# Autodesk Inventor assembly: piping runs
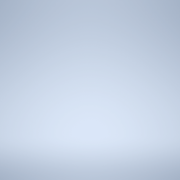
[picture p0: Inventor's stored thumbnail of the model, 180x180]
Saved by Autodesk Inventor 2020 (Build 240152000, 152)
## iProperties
ActiveState: False
Angle: UnInitValue
BendRadius: 12,700 mm
CouplingKey: UnInitValue
DefaultBendRadius: UnInitValue
Diameter: 1/2
DiameterType: Nominal
Elbow45Key: UnInitValue
Elbow90Key: UnInitValue
ElbowCustomKey: UnInitValue
EndFittingKey: v3#933069c9-73b6-4141-af99-628d4a97b2c2#1
Ending: UnInitValue
FittingMaterial: UnInitValue
FittingStandard: UnInitValue
FlangeKey: UnInitValue
Gap: UnInitValue
GasketKey: UnInitValue
ID: 1,27
IntermediateSegmentsInc: UnInitValue
IntermediateSegmentsMax: UnInitValue
IntermediateSegmentsMin: UnInitValue
IsButtWelded: UnInitValue
IsFlanged: UnInitValue
IsSelfDraining: UnInitValue
Material: UnInitValue
MixedUnits: UnInitValue
Name: Hydraulická hadice - SAE přírubové spojky
OD: 2,2352
PipeKey: v3#d489867e-ac9b-47ea-b952-0a1b885f66be#4
PipeType: Flexible Hose
PipingComponentColor: As Material
RoundUpValue: 3,175 mm
RouteDirection45: UnInitValue
RouteDirection90: UnInitValue
Schedule: ID=0.5
ShowGap: UnInitValue
Standard: UnInitValue
StartFittingKey: v3#933069c9-73b6-4141-af99-628d4a97b2c2#1
SuppressEndFitting: False
SuppressStartFitting: False
TerminationSegmentsInc: UnInitValue
TerminationSegmentsMax: UnInitValue
TerminationSegmentsMin: UnInitValue
UseFlangsForCouplings: UnInitValue
UseSubASM: True
_ComponentInfo: <CS><C N="Pipe" R="1.117600" OR="1.117600" IR="0.635000" PL="PL" PartType="" SymKey="" PN="Parker Hydraulic Hose - No Skive 1/2"><CO N="1"><FE V="0"/><FD V="0"/
BendRadius: UnInitValue
Diameter: M40
Elbow45Key: v3#97879d80-057e-491b-840b-74a9b3a7cf63#17
Elbow90Key: v3#ace818b0-7b7c-4ad9-b19c-6da358a202c1#17
EndFittingKey: UnInitValue
ID: UnInitValue
IntermediateSegmentsInc: 1,000 mm
IntermediateSegmentsMax: 5000,000 mm
IntermediateSegmentsMin: 60,000 mm
IsButtWelded: False
IsFlanged: False
IsSelfDraining: False
MixedUnits: False
Name: DIN 2458/DIN 2605 -Ocelové potrubí svařované a tvarovky
OD: UnInitValue
PipeKey: v3#dcef2839-8903-4c98-a96c-b861f5d9bb7f#98
PipeType: Rigid Pipe
RoundUpValue: UnInitValue
RouteDirection45: True
RouteDirection90: True
Schedule: ID=30.7
StartFittingKey: UnInitValue
SuppressEndFitting: UnInitValue
SuppressStartFitting: UnInitValue
TerminationSegmentsInc: 1,000 mm
TerminationSegmentsMax: 5000,000 mm
TerminationSegmentsMin: 60,000 mm
UseSubASM: UnInitValue
_ComponentInfo: <CS><C N="Pipe" R="2.415000" IR="1.535000" PL="PL" PN="DIN 2458 Pipe 48.3 x 8.8"><CO N="1"><FE V="2"/><FD V="0"/><ET V="Welded"/><NS V="M40"/><MA V="0.000000"/>
CouplingKey: v3#29993622-4c6a-437e-8b8c-43a0846f8735#1
Elbow45Key: v3#d7b5d569-4a12-4d65-ba55-12203d6ac7ed#1
Elbow90Key: v3#25d2a8db-6517-4627-a5a4-9d27e4d26b9b#1
IntermediateSegmentsInc: 2,540 mm
IntermediateSegmentsMax: 2540,000 mm
IntermediateSegmentsMin: 25,400 mm
Name: ASTM D 1785-ASTM D 2466 -  PVC potrubí spojované a tvarovky
PipeKey: v3#4bf12049-4375-491b-8f13-d4ee0c517c57#1
Schedule: 40
TerminationSegmentsInc: 2,540 mm
TerminationSegmentsMax: 2540,000 mm
TerminationSegmentsMin: 25,400 mm
_ComponentInfo: <CS><C N="Pipe" R="1.066800" IR="0.789940" PL="PL" PN="ASTM D 1785 Pipe 1/2 - Schedule 40"><CO N="1"><FE V="0"/><FD V="0"/><ET V="Jointed"/><NS V="1/2"/><MA V="
CouplingKey: v3#ed415c76-4cec-44a3-ba67-72e47bf70384#4
Elbow45Key: v3#2e5fd082-3851-4eb0-bde1-6c7078a7d72b#4
Elbow90Key: v3#82a08401-12d7-413b-b7f9-9cf3b607be7b#4
IntermediateSegmentsMax: 5080,000 mm
Name: ASTM A53/A53M-ASME B16.11 - Ocelové potrubí svařované
PipeKey: v3#4ce5e9fa-6da0-4801-ac02-ee7a0fb518d6#7
TerminationSegmentsMax: 5080,000 mm
_ComponentInfo: <CS><C N="Pipe" R="1.066800" IR="0.789940" PL="PL" PN="ASTM A 53/A 53M Pipe 1/2 - Schedule 40"><CO N="1"><FE V="0"/><FD V="0"/><ET V="Welded"/><NS V="1/2"/><MA 
CouplingKey: v3#b06656e5-2b55-488c-bcf0-6a90c79c4683#2
Elbow45Key: v3#421a8b99-1721-409a-bc3b-c00889561754#1
Elbow90Key: v3#17490b17-1dd8-40fc-8de7-1a70c3bab2d7#1
Name: ISO 4065-ISO 3633 - PVC potrubí a tvarovky
PipeKey: v3#4f84f716-5ba0-45ef-967a-c32c3d7345ce#70
Schedule: S40
_ComponentInfo: <CS><C N="Pipe" R="2.000000" IR="1.950000" PL="PL" PN="ISO 4065 Pipe 40 x 0.5 S40"><CO N="1"><FE V="0"/><FD V="0"/><ET V="Jointed"/><NS V="M40"/><MA V="6.000000
CouplingKey: v3#771d4942-b9e7-43bc-9d41-ab12a9580492#3
Elbow45Key: v3#626cc28c-1a24-4045-be0d-40d896dc828d#3
Elbow90Key: v3#bc6b44ab-9235-4590-b699-74498030a1ff#3
IntermediateSegmentsMin: 50,800 mm
Name: ANSI/ASME B36.19M-ASME B16.3 - Potrubí se závity a litinovými tvarovkami
PipeKey: v3#323c0148-c750-449d-a0c6-11721f2a5046#1
Schedule: 40S
TerminationSegmentsMin: 50,800 mm
_ComponentInfo: <CS><C N="Pipe" R="1.066800" IR="0.789940" PL="PL" PN="ANSI/ASME B36.19M Pipe with Threaded Ends 1/2 - Schedule 40S"><CO N="1"><FE V="0"/><FD V="1"/><ET V="Thre
CouplingKey: v3#181262db-c004-4877-bc40-c64b931a44f6#3
Elbow45Key: v3#960407aa-00b9-4d72-aae7-d50595845cfd#3
Elbow90Key: v3#6c92b367-65e9-486b-b952-db434ae2548d#3
IntermediateSegmentsMin: 20,000 mm
Name: JIS G 3442/JIS B 2301  Ocelové potrubí se závity a litinové tvarovky
PipeKey: v3#9964fba4-9d5a-4d75-85a8-e38022ccdce1#2
Schedule: ID=16.1
TerminationSegmentsMin: 20,000 mm
_ComponentInfo: <CS><C N="Pipe" R="1.085000" IR="0.805000" PL="PL" PN="JIS G 3442 Pipe with Threaded Ends 21.7 x 2.8"><CO N="1"><FE V="0"/><FD V="1"/><ET V="Threaded"/><NS V="1
Elbow45Key: v3#81684a3f-f2a4-4fe6-95b1-f067ddead22f#1
Elbow90Key: v3#451ae64e-c79d-4cba-b533-c09b8090ecb2#1
IntermediateSegmentsInc: 10,000 mm
IntermediateSegmentsMax: 9000,000 mm
IntermediateSegmentsMin: 1000,000 mm
Name: ISO 2531 - Potrubí z tvárné litiny s přírubami a tvarovkami
PipeKey: v3#f52fbdcb-ece8-4303-8b76-5dbe8c7f2f9c#16
Schedule: PN10
TerminationSegmentsInc: 10,000 mm
TerminationSegmentsMax: 9000,000 mm
TerminationSegmentsMin: 1000,000 mm
_ComponentInfo: <CS><C N="Pipe" R="2.700000" IR="2.000000" PL="PL" PN="ISO 2531 Pipe with Integrally Cast Flanges DN40 PN 10"><CO N="1"><FE V="0"/><FD V="0"/><ET V="Flanged"/><
EndFittingKey: v3#c5e461f5-5e73-4f2e-8c1e-4358d4d6f46c#4
Name: Hydraulická hadice - s vnitřním závitem - otočné
StartFittingKey: v3#c5e461f5-5e73-4f2e-8c1e-4358d4d6f46c#4
Angle: 92,00 deg
Diameter: 1
Elbow45Key: v3#bf26aa2a-f3dd-474c-8758-922a145c2b02#15
Elbow90Key: v3#3e93288f-9bb7-4e46-9d6b-544f8c20ca1c#3
ElbowCustomKey: v3#1f3bd44a-47ab-42f9-b3e0-74afa0c3f0ca#3
Gap: 2,388 mm
IntermediateSegmentsInc: 0.00001 in
IsButtWelded: True
IsSelfDraining: True
Name: ASME BPE - Ocelová trubka svařovaná na tupo/
PipeKey: v3#b10c956f-6fc6-429e-8056-0864a8581764#35
Schedule: ID=0.87
ShowGap: True
TerminationSegmentsInc: 0.00001 in
_ComponentInfo: <CS><C N="Pipe" R="1.270000" OR="1.270000" IR="1.104900" PL="PL" PartType="pipe" SymKey="" PN="ASTM A 269 Tube with Welded ends 1 x 0.87"><CO N="1"><FE V="2"/><
EndFittingKey: v3#c8250148-a7b6-458b-b7bd-3b56763ca7cc#13
Name: Hydraulická hadice - s vnějším kuželovým závitem
StartFittingKey: v3#c8250148-a7b6-458b-b7bd-3b56763ca7cc#13
CouplingKey: v3#7e56b2cb-a132-4546-b8a7-a14538454b94#3
Elbow45Key: v3#a96c5204-26e4-4bb2-b8f1-f0623fbc94bb#2
Elbow90Key: v3#b72bb08b-ad33-47cc-a03d-7f3d76c6616b#3
Name: ISO 7598/ISO 49 -  Ocelové potrubí se závity a litinovými tvarovkami
PipeKey: v3#1052637f-74b5-47f4-adeb-d4e8d3fa53b8#1
_ComponentInfo: <CS><C N="Pipe" R="1.065000" IR="0.805000" PL="PL" PN="ISO 7598 Tube with Threaded Ends DN15"><CO N="1"><FE V="0"/><FD V="1"/><ET V="Threaded"/><NS V="1/2"/><MA
Diameter: 6
Elbow90Key: v3#6a678020-d9d9-4685-bba9-906b9a167083#10
FlangeKey: v3#c11442d2-c568-438f-a870-8ac9b5b636cb#10
GasketKey: v3#2a41914c-f5fb-4682-9c6a-1870d826d3d0#23
IntermediateSegmentsMin: 76,200 mm
IsFlanged: True
Name: ASTM A 53/A-ASME B16.5 – Ocelové trubky přírubové závitové
PipeKey: v3#c5bd7d28-cdb3-4507-9f3d-c2787d93fe8a#40
RouteDirection45: False
TerminationSegmentsMin: 76,200 mm
_ComponentInfo: <CS><C N="Elbow90" ER="21.590000" S1="21.590000" S2="21.590000" D1="0.000000" D2="0.000000" PartType="fitting" SymKey="ELFL"><CO N="1"><FE V="2"/><FD V="1"/><ET
Elbow90Key: v3#97ecdcaf-8aa3-4fb0-8b6a-3da783de2ad5#108
Gap: 1,575 mm
Name: ASTM A 53/A-ASME B16.9 – Ocelové trubky svařované na tupo
PipeKey: v3#4ce5e9fa-6da0-4801-ac02-ee7a0fb518d6#77
_ComponentInfo: <CS><C N="Elbow90" ER="15.240000" S1="15.240000" S2="15.240000" D1="0.000000" D2="0.000000" PartType="fitting" SymKey="ELBW"><CO N="1"><FE V="2"/><FD V="0"/><ET
EndFittingKey: v3#b50cb43e-68c0-48ac-8e25-7ef224ce0e6c#3
Name: Hydraulické hadice - s vnějším přímým závitem
StartFittingKey: v3#b50cb43e-68c0-48ac-8e25-7ef224ce0e6c#3
ActiveState: True
CouplingKey: v3#52ad3977-2b89-4007-a6a6-7626bac0ae85#4
Elbow45Key: v3#5c2ab816-abcb-49a6-a106-4733af000f51#4
Elbow90Key: v3#160eac10-3e6f-4b5c-839c-61eee0d373dc#4
Name: ASME B36.10M-ASME B16.11 - Ocelové potrubí se závity
PipeKey: v3#4a736116-503a-44ad-a922-868ac6b46736#1
Schedule: 30
_ComponentInfo: <CS><C N="Pipe" R="1.066800" IR="0.825500" PL="PL" PN="ASME B36.10M Pipe with Threaded Ends 1/2 - Schedule 30"><CO N="1"><FE V="0"/><FD V="1"/><ET V="Threaded"/
Name: Hydraulická hadice - bez tvarovek
SuppressEndFitting: True
SuppressStartFitting: True
Created: 2006-09
Part Number: piping runs
Document SubType Name: Tube & Pipe
Manufacturer: Standard
Standards Organization: Custom
Material: Všeobecné
EndFittingKey: v3#cc3bd835-95a2-497d-9893-176cd9c426f6#7
Name: Hydraulická hadice - s vnitřním kuželovým závitem
StartFittingKey: v3#cc3bd835-95a2-497d-9893-176cd9c426f6#7
CouplingKey: v3#0dc1ae02-7bbf-4ccf-8498-581434b0a765#3
DefaultBendRadius: 50,800 mm
IntermediateSegmentsMin: 0,000 mm
Name: ASTM B 88-ASME B16.22 -  Měděné potrubí pájené
PipeKey: v3#44b182c9-4bce-4825-bb4d-596143122252#7
PipeType: Tubing
Schedule: L
TerminationSegmentsMin: 0,000 mm
_ComponentInfo: <CS><C N="Pipe" R="0.793750" IR="0.692150" PL="PL" PN="ASTM B 88 Tube 1/2 - Type L"><CO N="1"><FE V="0"/><FD V="0"/><ET V="Soldered"/><NS V="1/2"/><MA V="2.5400
FlangeKey: v3#24991861-26e3-4c21-a713-f46e314eddd5#10
Name: ASTM A 53/A 53M - Ocelová trubka svařovaná na tupo/přírubová trubka
UseFlangsForCouplings: False
_ComponentInfo: <CS><C N="Pipe" R="8.413750" OR="8.413750" IR="7.702550" PL="PL" PartType="pipe" SymKey="" PN="ASTM A 53/A 53M Pipe 6 - Schedule 40"><CO N="1"><FE V="2"/><FD V=
CouplingKey: v3#eaa8de87-dc67-4eca-ba7e-4267a30f8f7f#2
Elbow45Key: v3#2769403e-a4fd-4a4c-8e4c-659ea845bd78#2
Elbow90Key: v3#c4513a61-3106-4a78-baf9-a1badd100245#2
IntermediateSegmentsMax: 2500,000 mm
Name: JIS K 6741/JIS K 6739 -PVC-U potrubí spojované a tvarovky
PipeKey: v3#45338dd0-af69-48c0-a2ed-8ade33a08701#5
Schedule: VP
TerminationSegmentsMax: 2500,000 mm
_ComponentInfo: <CS><C N="Pipe" R="2.400000" IR="2.040000" PL="PL" PN="JIS K 6741 Pipe VP 40"><CO N="1"><FE V="0"/><FD V="1"/><ET V="Jointed"/><NS V="M40"/><MA V="4.000000"/><M
Name: DIN 8062/DIN 8063 - PVC-U potrubí spojované a tvarovky
RoutePreview: Solid
Schedule: 5
IntermediateSegmentsMin: 60.000 mm
IntermediateSegmentsMax: 5000.000 mm
IntermediateSegmentsInc: 1.000 mm
TerminationSegmentsMin: 60.000 mm
TerminationSegmentsMax: 5000.000 mm
TerminationSegmentsInc: 1.000 mm
SolidRoutePreviewColor: 12632064
PipeKey: v3#3d294dc7-89c3-4c37-a0ae-28c15a73bfd0#13
CouplingKey: v3#3edf83e2-464b-4b31-84c5-c329ffbf2a4f#5
Elbow90Key: v3#fbd68fd5-590c-4cb5-8c20-9e9bdd396a04#5
Elbow45Key: v3#2f597a97-b15b-49d4-87cb-7bfe69eb62ee#5
_ComponentInfo: <CS><C N="Pipe" R="2.000000" IR="1.700000" PL="PL" PN="DIN 8062 Pipe 40 x 3"><CO N="1"><FE V="0"/><FD V="0"/><ET V="Jointed"/><NS V="M40"/><MA V="8.000000"/><MI
count: 52
Refkey_Axis1_Context: 2|0|0|0|1|0|0|0|
Refkey_Axis1: 6|0|0|0|44|0|0|0|78|0|65|0|77|0|69|0|83|0|10|0|67|0|111|0|108|0|111|0|114|0|115|0|10|0|49|0|58|0|10|0|10|0|69|0|78|0|68|0|10|0|0|0|
Refkey_Axis2_Context: 2|0|0|0|1|0|0|0|
Refkey_Axis2: 6|0|0|0|88|0|0|0|78|0|65|0|77|0|69|0|83|0|10|0|67|0|111|0|108|0|111|0|114|0|115|0|10|0|49|0|58|0|82|0|111|0|117|0|116|0|101|0|32|0|85|0|73|0|32|0|84|0|111|0|111
Refkey_Axis3_Context: 2|0|0|0|1|0|0|0|
Refkey_Axis3: 6|0|0|0|88|0|0|0|78|0|65|0|77|0|69|0|83|0|10|0|67|0|111|0|108|0|111|0|114|0|115|0|10|0|49|0|58|0|82|0|111|0|117|0|116|0|101|0|32|0|85|0|73|0|32|0|84|0|111|0|111
Refkey_Ext_Context: 2|0|0|0|1|0|0|0|
Refkey_Ext: 6|0|0|0|92|0|0|0|78|0|65|0|77|0|69|0|83|0|10|0|67|0|111|0|108|0|111|0|114|0|115|0|10|0|49|0|58|0|82|0|111|0|117|0|116|0|101|0|32|0|85|0|73|0|32|0|84|0|111|0|111
Refkey_Snap_Context: 2|0|0|0|1|0|0|0|
Refkey_Snap: 6|0|0|0|84|0|0|0|78|0|65|0|77|0|69|0|83|0|10|0|67|0|111|0|108|0|111|0|114|0|115|0|10|0|49|0|58|0|82|0|111|0|117|0|116|0|101|0|32|0|85|0|73|0|32|0|84|0|111|0|111
CouplingKey: v3#12b64993-10e6-4915-8315-0c0cce209ad0#8
Elbow45Key: v3#28e76e79-e22c-40ab-8be2-ff545b1407c5#8
Elbow90Key: v3#1f65ece3-c41a-48d4-8661-909ed34ade86#8
Name: JIS G 3458/JIS B 2316 - Ocelové potrubí svařované a tvarovky
PipeKey: v3#da14b0ab-0b36-4851-8d66-8c9cd0bcbe86#23
Schedule: 80
_ComponentInfo: <CS><C N="Pipe" R="2.430000" IR="1.920000" PL="PL" PN="JIS G 3458 Pipe 40 A x Sch 80"><CO N="1"><FE V="0"/><FD V="1"/><ET V="Welded"/><NS V="M40"/><MA V="0.0000
CouplingKey: v3#d2599e7a-1865-48da-a234-5418a1cd5dfe#3
Elbow45Key: v3#6ce5b1be-37aa-4928-b23a-0df64e6ddf38#2
Elbow90Key: v3#9fba244e-81ed-4fc6-a9ac-7eb372fa3ffe#3
Name: DIN 2458/DIN EN 10242 - Ocelové potrubí se závity a litinové tvarovky
PipeKey: v3#d689fd5f-ac5a-46d7-a883-3089b2f6e0a4#28
Schedule: ID=12.3
_ComponentInfo: <CS><C N="Pipe" R="1.065000" IR="0.615000" PL="PL" PN="DIN 2458 Pipe with Threaded Ends 21.3 x 4.5"><CO N="1"><FE V="0"/><FD V="1"/><ET V="Threaded"/><NS V="1/2
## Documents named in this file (1)
- C:\Users\Smoke\Desktop\csy\piping runs.iam
